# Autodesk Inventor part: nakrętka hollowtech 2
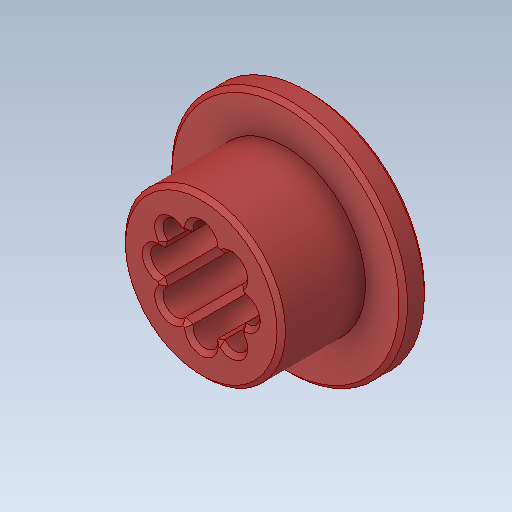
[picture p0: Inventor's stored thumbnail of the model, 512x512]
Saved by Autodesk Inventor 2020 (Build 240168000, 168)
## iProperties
Created: 2017-10
Part Number: nakrętka hollowtech 2
Material: Ogólny
Document SubType Name: Modeling
Designer: Tomasz
Density: 1 g/cm^3
Appearance: Domyślna
Sending System: SolidWorks 2017
Last Author: Tomasz
Last Saved: 2017-10-01
Author: Tomasz
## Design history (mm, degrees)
chamfer "Chamfer2"
node "Bryła1"
